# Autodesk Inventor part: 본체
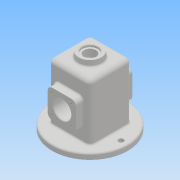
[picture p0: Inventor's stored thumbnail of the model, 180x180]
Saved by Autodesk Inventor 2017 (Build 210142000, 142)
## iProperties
Part Number: 본체
Material: 알루미늄 6061
Document SubType Name: 판금
Designer: user
Density: 2.7 g/cm^3
Sheet Metal Rule: 기본값_mm
Appearance: 알루미늄 - 평지
Mass: 304.335 g
Surface Area: 949.017 cm^2
Volume: 304.335 cm^3
Author: user
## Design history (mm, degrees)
sketch "스케치1"
  geometry: L1 (-37, -37)-(37, -37); L2 (37, -37)-(37, 37); L3 (37, 37)-(-37, 37); L4 (-37, 37)-(-37, -37); L5 (-37, -37)-(37, 37); L6 (37, -37)-(-37, 37); 1 further point
  constraints: 12 end point, 2 midpoint, 2 parallel, 1 horizontal, 1 perpendicular
  dimensions: "d0" = 74 distance of L2.end L3.end; "d1" = 74 distance of L1.end L2.end
extrude "돌출1" new body sketch "스케치1" distance "d2" = 110; taper "d3" = 0 deg
sketch "스케치2"
  geometry: C1 r 67 at (0, 0); 1 further point
  constraints: 1 centre point, 1 coincident
  dimensions: "d4" = 134 diameter of C1
extrude "돌출2" join sketch "스케치2" distance "d5" = 10; taper "d6" = 0 deg
node "작업 평면1"
sketch "스케치3"
  geometry: A1 r 20 centre (0, 0) between (-20, 0) and (20, 0); 1 further point
  constraints: 2 horizontal alignment, 2 point on circle, 1 centre point, 1 coincident
  dimensions: "d8" = 40 diameter of A1
sketch "스케치4"
  geometry: L1 (20, 120)-(23.555, 86.18); L2 (-20, 120)-(-23.153, 90); L3 (20, 120)-(-20, 120); L4 (-37, 10)-(37, 10) reference; L5 (37, 10)-(37, 110) reference; L6 (-37, 110)-(37, 110) reference; L7 (-37, 10)-(-37, 110) reference; L8 (-23.153, 90)-(31.164, 90); 3 further points
  constraints: 8 end point, 2 horizontal, 2 point on line, 1 coincident
  dimensions: "d9" = 6 deg angle of L7 L2; "d10" = 6 deg angle of L5 L1; "d11" = 30 distance between parallel lines of L8 L3
  node "투영된 루프1"
node "작업 평면2"
sketch "스케치5"
  geometry: 4 further points
  constraints: 1 coincident, 1 horizontal alignment, 2 other
feature "로프트1" sketch "스케치5" dims "d13" = 0, "d14" = 90 deg, "d15" = 0, "d16" = 90 deg
sketch "스케치6"
  geometry: L1 (25, 80)-(-25, 80); L2 (-25, 80)-(-25, 30); L3 (-25, 30)-(25, 30); L4 (25, 30)-(25, 80); L5 (25, 80)-(-25, 30); L6 (-25, 80)-(25, 30); 4 further points
  constraints: 12 end point, 4 midpoint, 2 parallel, 1 horizontal, 1 perpendicular, 1 vertical alignment
  dimensions: "d17" = 50 distance of L1.start L1.end; "d18" = 50 distance of L1.end L2.end; "d19" = 55 distance of point (0, 0) point (0, 55)
extrude "돌출3" join sketch "스케치6" stored distance "d20" = 100; taper "d21" = 0 deg
sketch "스케치7"
  geometry: L1 (32, -32)-(-32, -32); L2 (-32, -32)-(-32, 32); L3 (-32, 32)-(32, 32); L4 (32, 32)-(32, -32); L5 (32, -32)-(-32, 32); L6 (-32, -32)-(32, 32); C1 r 67 at (0, 0) reference
  constraints: 12 end point, 2 midpoint, 2 parallel, 1 horizontal, 1 perpendicular
  dimensions: "d22" = 64 distance of L1.end L2.end; "d23" = 64 distance of L2.end L3.end
extrude "돌출4" cut sketch "스케치7" distance "d24" = 105; taper "d25" = 0 deg
sketch "스케치8"
  geometry: L1 (-32, 0)-(-32, 105) reference; L2 (-50, 80)-(-50, 30) reference; L3 (50, 30)-(50, 80) reference; L4 (-50, 55)-(50, 55); L5 (-32, 80)-(-25, 77.452); L6 (-25, 77.452)-(-25, 55); L7 (-32, 80)-(-32, 55); 1 further point
  constraints: 8 end point, 4 point on line, 2 midpoint, 1 perpendicular
  dimensions: "d26" = 110 deg angle of L1 L5; "d27" = 7 distance between parallel lines of L6 L1; "d28" = 50 diameter of L5.start L4
revolve "회전1" sketch "스케치8" stored, may be unused: angle "d29" = 90 deg
sketch "스케치9"
  geometry: L1 (25, 80)-(-25, 80) reference; L2 (-25, 80)-(-25, 30) reference; L3 (-25, 30)-(25, 30) reference; L4 (25, 30)-(25, 80) reference; L5 (-25, 55)-(25, 55); C1 r 16 at (0, 55); 1 further point
  constraints: 3 midpoint, 2 end point, 1 centre point
  dimensions: "d30" = 32 diameter of C1
extrude "돌출5" cut sketch "스케치9" distance "d31" = 189; taper "d32" = 0 deg
hole "구멍1" diameter "d35" = 21; stored, may be unused: countersink angle "d39" = 90 deg, drill point angle "d41" = 118 deg; dims "d33" = 10, "d34" = 10, "d36" = 6, "d37" = 28, "d38" = 4, "d40" = 0.5 (derived)
chamfer "모따기1" distance "d42" = 1; stored, may be unused: second distance "d43" = 2, angle "d44" = 45 deg
fillet "모깎기1" dims "d45" = 3
fillet "모깎기2" dims "d46" = 3
sketch "스케치10"
  geometry: L1 (-17, 38)-(17, 38); L2 (17, 38)-(17, 72); L3 (17, 72)-(-17, 72); L4 (-17, 72)-(-17, 38); L5 (-17, 38)-(17, 72); L6 (17, 38)-(-17, 72); C1 r 17 at (0, 55) reference; 5 further points
  constraints: 12 end point, 4 coincident, 2 midpoint, 2 parallel, 1 horizontal, 1 perpendicular
  dimensions: "d47" = 34 distance of L2.end L3.end; "d48" = 34 distance of L1.end L2.end
hole "구멍2" sketch "스케치10" at (-17, 72), (17, 72), (-17, 38), (17, 38) diameter "d49" = 3.242; stored, may be unused: countersink angle "d53" = 90 deg, drill point angle "d55" = 118 deg; dims "d50" = 8, "d51" = 28, "d52" = 4, "d54" = 10
fillet "모깎기3" dims "d56" = 8
fillet "모깎기4" dims "d57" = 8
fillet "모깎기5" dims "d58" = 8
fillet "모깎기6" dims "d59" = 3
sketch "스케치11"
  geometry: C1 r 64 at (0, 0) reference; A1 r 55 centre (0, 0) between (55, 0) and (-55, 0)
  constraints: 2 horizontal alignment, 2 point on circle, 1 centre point, 1 coincident
  dimensions: "d60" = 110 diameter of A1
hole "구멍3" sketch "스케치11" at (55, 0), (-55, 0) diameter "d61" = 9; stored, may be unused: countersink angle "d65" = 90 deg, drill point angle "d67" = 118 deg; dims "d62" = 8, "d63" = 28, "d64" = 4, "d66" = 10
sketch "스케치12"
  geometry: L1 (49, -18)-(9, -18) reference; 2 further points
  constraints: 1 vertical alignment, 1 other
  dimensions: "d68" = 28 distance from line of point (29, 10) L1
feature "엠보싱1" sketch "스케치12" dims "d8" = 40, "d69" = 0.5, "d70" = 0, "MinimumRemnant" = 1 (derived)
fillet "모깎기7" dims "d71" = 3
node "솔리드1"
mirror "미러1"
mirror "미러2"
node "투영된 루프2"
other parameters: "K계수" = 4.4, "BendRadius" = 0.5 (derived), "BendReliefWidth" = 0.5 (derived), "BendReliefDepth" = 0.25 (derived), "CornerReliefSize" = 2 (derived), "SeamGap" = 0.01, "TransitionRadius" = 0.5 (= BendRadius), "d12" = 90 deg
